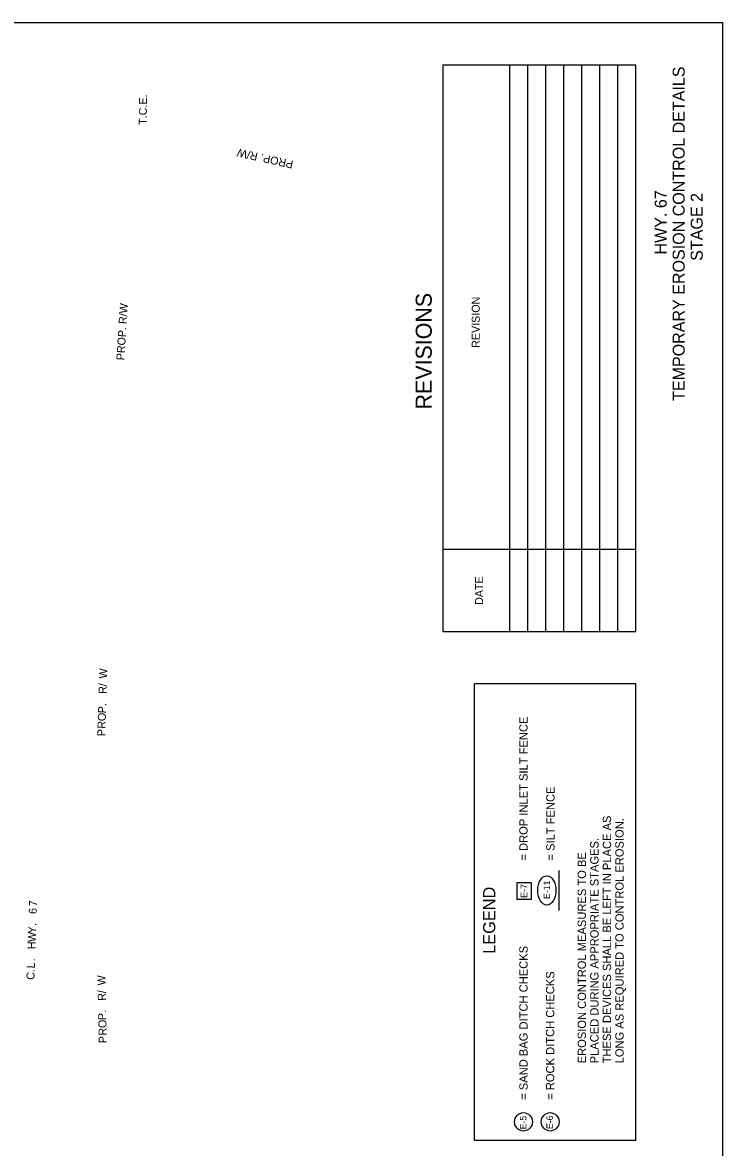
# Model space of a CAD drawing. Extents: x 991974 to 993016, y 1842702 to 1844298.
# Drawn here: x 992492 to 993016, y 1843454 to 1844298 of the extents above; entities that cross this region are included whole.
import ezdxf

# ---------------------------------------------------------------- set-up
doc = ezdxf.new("R2010")
doc.units = 0
for name, color, linetype in [('1', 7, 'Continuous'), ('60', 7, 'Continuous'), ('Default', 7, 'Continuous'), ('G-Border-Sheet', 7, 'Continuous'), ('Level 1', 7, 'Continuous'), ('Level 44', 7, 'Continuous'), ('R_Draft', 7, 'Continuous')]:
    doc.layers.add(name, color=color, linetype=linetype)

msp = doc.modelspace()

# ---------------------------------------------------------------- linework, layer by layer
at = {"layer": '1'}
msp.add_lwpolyline([(992862.32, 1843640.1), (992862.32, 1843652.85), (992872.83, 1843652.85), (992872.83, 1843640.1)], close=True, dxfattribs=at)
at = {"layer": 'Default'}
msp.add_lwpolyline([(993016.34, 1842702.47), (991974.02, 1842702.47), (991974.02, 1843999.48), (992023.57, 1843999.48), (992023.57, 1844170.33), (992171.07, 1844170.33), (992171.07, 1844297.83), (993016.34, 1844297.83)], close=True, dxfattribs=at)
msp.add_lwpolyline([(993016.34, 1842702.47), (991974.02, 1842702.47), (991974.02, 1843999.48), (992023.57, 1843999.48), (992023.57, 1844170.33), (992171.07, 1844170.33), (992171.07, 1844297.83), (993016.34, 1844297.83)], close=True, dxfattribs=at)
at = {"layer": 'G-Border-Sheet'}
for p, q in [((992951.38, 1843801.93), (992830.33, 1843801.93)), ((992830.33, 1843459.27), (992830.33, 1843801.93)), ((992951.38, 1843459.27), (992951.38, 1843801.93)), ((992951.38, 1843459.27), (992830.33, 1843459.27))]:
    msp.add_line(p, q, dxfattribs=at)
at = {"layer": 'Level 1'}
for centre, major_axis, ratio in [((992884.7, 1843646.9), (0, 10.96), 0.622952), ((992867.16, 1843473.37), (0, -6.88), 0.97521), ((992887.16, 1843473.37), (0, -6.88), 0.97521)]:
    msp.add_ellipse(centre, major_axis=major_axis, ratio=ratio, dxfattribs=at)
at = {"layer": 'Level 44'}
msp.add_lwpolyline([(992894.03, 1843631.84), (992894.02, 1843661.96)], dxfattribs=at)
at = {"layer": 'R_Draft'}
for p, q in [((992806.88, 1843840.99), (992806.88, 1844265.99)), ((992806.88, 1844265.99), (992951.38, 1844265.99)), ((992856.88, 1843840.99), (992856.88, 1844265.99)), ((992870.38, 1843840.99), (992870.38, 1844265.99)), ((992883.88, 1843840.99), (992883.88, 1844265.99)), ((992897.38, 1843840.99), (992897.38, 1844265.99)), ((992897.38, 1843840.99), (992897.38, 1844265.99)), ((992910.88, 1843840.99), (992910.88, 1844265.99)), ((992924.38, 1843840.99), (992924.38, 1844265.99)), ((992937.88, 1843840.99), (992937.88, 1844265.99)), ((992951.38, 1843840.99), (992951.38, 1844265.99)), ((992806.88, 1843902.8), (992951.38, 1843902.8)), ((992806.88, 1843840.99), (992951.38, 1843840.99))]:
    msp.add_line(p, q, dxfattribs=at)

# ---------------------------------------------------------------- texts
at = {"layer": '1'}
msp.add_text('E-7 ', height=4.999, rotation=89.61212, dxfattribs=at).set_placement((992870.01, 1843641.26))
at = {"layer": '60'}
for s, p in [('TEMPORARY EROSION CONTROL DETAILS', (992988.01, 1844014.05)), ('HWY. 67 ', (992974.51, 1844123.82)), (' STAGE 2', (993001.51, 1844115.78))]:
    msp.add_text(s, height=9, rotation=90, dxfattribs=at).set_placement(p)
at = {"layer": 'Level 1'}
for s, height, p in [('= DROP INLET SILT FENCE', 6.25, (992870.26, 1843669.33)), ('= SILT FENCE', 6.25, (992890.48, 1843669.33)), ('THESE DEVICES SHALL BE LEFT IN PLACE AS ', 6.25, (992932.84, 1843517.24)), ('LONG AS REQUIRED TO CONTROL EROSION.', 6.25, (992942.25, 1843517.24)), ('PLACED DURING APPROPRIATE STAGES. ', 6.25, (992923.43, 1843517.24)), ('EROSION CONTROL MEASURES TO BE', 6.25, (992914.02, 1843517.24)), ('E-11 ', 4.876, (992887.1, 1843640.5)), ('= SAND BAG DITCH CHECKS', 6.25, (992870.28, 1843489.9)), ('= ROCK DITCH CHECKS', 6.25, (992890.28, 1843489.9)), ('E-5 ', 4.876, (992869.38, 1843467.73)), ('E-6 ', 4.876, (992889.29, 1843467.95))]:
    msp.add_text(s, height=height, rotation=90.00001, dxfattribs=at).set_placement(p)
at = {"layer": 'Level 44'}
msp.add_text('LEGEND', height=9.143, rotation=90.00001, dxfattribs=at).set_placement((992846.03, 1843599.41))
at = {"layer": 'R_Draft'}
for s, height, rotation, p in [('T.C.E.', 6, 89.40901, (992584.79, 1844221.09)), ('PROP. R/W', 6, 167.44815, (992695, 1844194.05)), ('REVISIONS', 12, 90, (992798.38, 1844007.65)), ('PROP. R/W', 6, 86.36556, (992567.94, 1844044.35)), ('REVISION', 6, 90, (992834.38, 1844053.86)), ('DATE', 6, 90, (992836.88, 1843861.06)), ('W', 6, 88.2004, (992554.98, 1843805.77)), ('/', 6, 88.2004, (992554.8, 1843799.91)), ('R', 6, 88.2004, (992554.62, 1843794.24)), ('P', 6, 88.2004, (992554.16, 1843779.65)), ('.', 6, 88.2004, (992554.34, 1843785.32)), ('R', 6, 88.2004, (992553.8, 1843768.13)), ('O', 6, 88.2004, (992553.98, 1843773.8)), ('P', 6, 88.2004, (992553.62, 1843762.47)), ('7', 6, 88.03611, (992502.43, 1843634.86)), ('6', 6, 88.03611, (992502.24, 1843629.19)), ('.', 6, 88.03611, (992501.93, 1843620.27)), ('W', 6, 88.03611, (992501.52, 1843608.09)), ('Y', 6, 88.03611, (992501.74, 1843614.51)), ('H', 6, 88.03611, (992501.33, 1843602.71)), ('L', 6, 88.03611, (992500.84, 1843588.4)), ('.', 6, 88.03611, (992501.03, 1843593.78)), ('C', 6, 88.03611, (992500.55, 1843579.81)), ('.', 6, 88.03611, (992500.74, 1843585.47)), ('W', 6, 91.21594, (992553.9, 1843575.77)), ('/', 6, 91.21594, (992554.03, 1843569.92)), ('R', 6, 91.21594, (992554.15, 1843564.25)), ('P', 6, 91.21594, (992554.46, 1843549.65)), ('.', 6, 91.21594, (992554.34, 1843555.32)), ('O', 6, 91.21594, (992554.58, 1843543.8)), ('R', 6, 91.21594, (992554.7, 1843538.13)), ('P', 6, 91.21594, (992554.82, 1843532.46))]:
    msp.add_text(s, height=height, rotation=rotation, dxfattribs=at).set_placement(p)

doc.saveas('drawing.dxf')
